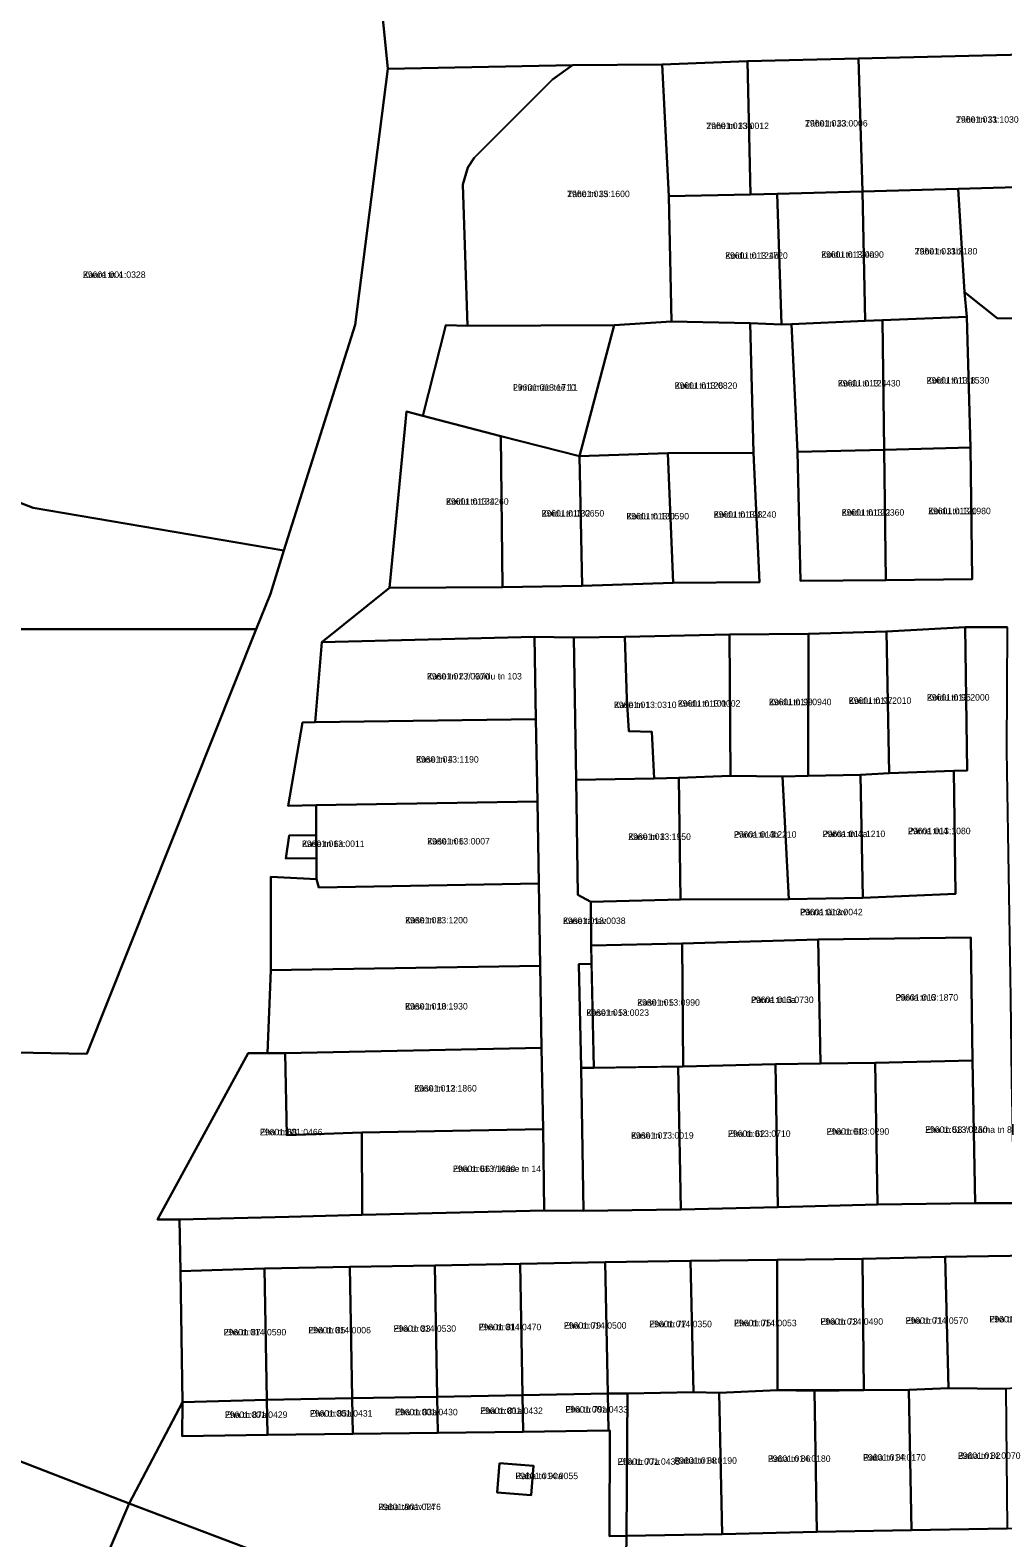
# Model space of a CAD drawing. Extents: x 518839 to 525192, y 6573164 to 6576561.
# Drawn here: x 523288.9 to 523514.2, y 6573652.7 to 6574001.8 of the extents above; entities that cross this region are included whole.
import ezdxf

# ---------------------------------------------------------------- set-up
doc = ezdxf.new("R2010")
doc.units = 0
for name, color, linetype in [('L_AADRESS', 7, 'Continuous'), ('PIIR', 7, 'Continuous'), ('TUNNUS', 7, 'Continuous')]:
    doc.layers.add(name, color=color, linetype=linetype)

msp = doc.modelspace()

# ---------------------------------------------------------------- linework, layer by layer
at = {"layer": 'PIIR'}
for points in [[(523179.73, 6573986.9), (523184.22, 6574005.85), (523276.05, 6574005.07), (523309.21, 6574005.43), (523309.74, 6574006.34), (523370.33, 6574007.54), (523371.79, 6573992.85), (523364.2, 6573933.56), (523347.71, 6573881.28), (523289.61, 6573891.15), (523234.3, 6573912.48), (523239.29, 6573978.07), (523222.16, 6573985.77)], [(523389.14, 6573966.07), (523390.31, 6573969.97), (523391.75, 6573972.24), (523409.91, 6573990.37), (523414.5, 6573993.67), (523435.27, 6573993.85), (523436.86, 6573963.35), (523437.44, 6573934.33), (523424.21, 6573933.47), (523390.19, 6573933.31)], [(523435.27, 6573993.85), (523455.07, 6573994.57), (523455.77, 6573963.73), (523436.86, 6573963.35)], [(523455.07, 6573994.57), (523480.74, 6573995.19), (523481.7, 6573964.38), (523461.92, 6573963.85), (523455.77, 6573963.73)], [(523480.74, 6573995.19), (523525.52, 6573996.29), (523525.53, 6573965.66), (523503.85, 6573965.03), (523481.7, 6573964.38)], [(523505.33, 6573941.1), (523503.85, 6573965.03), (523525.53, 6573965.66), (523525.92, 6573941.42), (523520.6, 6573934.94), (523512.9, 6573935.07)], [(523437.44, 6573934.33), (523436.86, 6573963.35), (523455.77, 6573963.73), (523461.92, 6573963.85), (523462.92, 6573933.6), (523455.7, 6573933.92)], [(523462.92, 6573933.6), (523461.92, 6573963.85), (523481.7, 6573964.38), (523482.35, 6573934.46), (523465.27, 6573933.72)], [(523482.35, 6573934.46), (523481.7, 6573964.38), (523503.85, 6573965.03), (523505.33, 6573941.1), (523505.87, 6573935.43), (523486.35, 6573934.6)], [(523164.89, 6573924.93), (523168.13, 6573938.02), (523234.3, 6573912.48), (523289.61, 6573891.15), (523347.71, 6573881.28), (523344.56, 6573871.27), (523341.27, 6573863.07), (523227.95, 6573863.09), (523197.91, 6573875.12), (523213.55, 6573906.24)], [(523416.19, 6573903.12), (523424.21, 6573933.47), (523437.44, 6573934.33), (523455.7, 6573933.92), (523456.42, 6573903.94), (523436.62, 6573903.87)], [(523465.27, 6573933.72), (523482.35, 6573934.46), (523486.35, 6573934.6), (523486.71, 6573904.58), (523466.63, 6573904.16)], [(523486.35, 6573934.6), (523505.87, 6573935.43), (523506.74, 6573905.15), (523486.71, 6573904.58)], [(523379.86, 6573912.46), (523385.21, 6573933.5), (523390.19, 6573933.31), (523424.21, 6573933.47), (523416.19, 6573903.12), (523397.97, 6573907.79)], [(523376.1, 6573913.49), (523379.86, 6573912.46), (523397.97, 6573907.79), (523398.35, 6573872.77), (523372.13, 6573872.63)], [(523416.19, 6573903.12), (523416.78, 6573873.13), (523398.35, 6573872.77), (523397.97, 6573907.79)], [(523416.78, 6573873.13), (523416.19, 6573903.12), (523436.62, 6573903.87), (523437.86, 6573873.83)], [(523436.62, 6573903.87), (523456.42, 6573903.94), (523457.86, 6573873.97), (523437.86, 6573873.83)], [(523466.63, 6573904.16), (523486.71, 6573904.58), (523487.11, 6573874.4), (523467.33, 6573874.29)], [(523486.71, 6573904.58), (523506.74, 6573905.15), (523507.11, 6573874.68), (523487.11, 6573874.4)], [(523356.5, 6573860.09), (523405.73, 6573861.31), (523406.06, 6573842.21), (523354.92, 6573841.56)], [(523405.73, 6573861.31), (523414.83, 6573861.12), (523415.36, 6573828.22), (523415.74, 6573801.54), (523418.77, 6573799.99), (523418.85, 6573789.88), (523418.94, 6573785.63), (523416, 6573785.54), (523416.55, 6573761.52), (523417.09, 6573728.42), (523408.01, 6573728.5), (523407.72, 6573747.32), (523407.37, 6573766.12), (523407.07, 6573785.14), (523406.73, 6573804.17), (523406.39, 6573823.19), (523406.06, 6573842.21)], [(523414.83, 6573861.12), (523426.68, 6573861.32), (523427.15, 6573846.93), (523427.58, 6573839.5), (523432.87, 6573839.31), (523433.44, 6573828.47), (523415.36, 6573828.22)], [(523418.77, 6573799.99), (523439.53, 6573800.47), (523464.67, 6573800.57), (523481.77, 6573800.88), (523503.2, 6573801.82), (523502.82, 6573830.27), (523505.95, 6573830.39), (523505.5, 6573863.51), (523515.24, 6573863.54), (523515.05, 6573835.01), (523515.36, 6573815.85), (523515.68, 6573796.84), (523516, 6573777.76), (523516.2, 6573758.68), (523516.72, 6573730.15), (523507.79, 6573730.18), (523507.17, 6573763.2), (523506.82, 6573791.66), (523471.42, 6573791.21), (523439.93, 6573790.32), (523418.85, 6573789.88)], [(523432.87, 6573839.31), (523427.58, 6573839.5), (523427.15, 6573846.93), (523426.68, 6573861.32), (523450.86, 6573861.88), (523451.16, 6573829.1), (523439.14, 6573828.67), (523433.44, 6573828.47)], [(523469.17, 6573861.99), (523469.15, 6573829.11), (523463.15, 6573829), (523451.16, 6573829.1), (523450.86, 6573861.88)], [(523469.17, 6573861.99), (523487.28, 6573862.58), (523487.87, 6573829.74), (523481.25, 6573829.33), (523469.15, 6573829.11)], [(523487.28, 6573862.58), (523505.5, 6573863.51), (523505.95, 6573830.39), (523502.82, 6573830.27), (523487.87, 6573829.74)], [(523406.39, 6573823.19), (523355.15, 6573822.36), (523348.65, 6573822.17), (523351.99, 6573841.51), (523354.92, 6573841.56), (523406.06, 6573842.21)], [(523481.25, 6573829.33), (523487.87, 6573829.74), (523502.82, 6573830.27), (523503.2, 6573801.82), (523481.77, 6573800.88)], [(523415.74, 6573801.54), (523415.36, 6573828.22), (523433.44, 6573828.47), (523439.14, 6573828.67), (523439.53, 6573800.47), (523418.77, 6573799.99)], [(523464.67, 6573800.57), (523439.53, 6573800.47), (523439.14, 6573828.67), (523451.16, 6573829.1), (523463.15, 6573829)], [(523464.67, 6573800.57), (523463.15, 6573829), (523469.15, 6573829.11), (523481.25, 6573829.33), (523481.77, 6573800.88)], [(523406.73, 6573804.17), (523355.78, 6573803.27), (523355.27, 6573805.23), (523355.23, 6573810.03), (523355.2, 6573815.35), (523355.15, 6573822.36), (523406.39, 6573823.19)], [(523355.23, 6573810.03), (523348.14, 6573809.95), (523348.94, 6573815.29), (523355.2, 6573815.35)], [(523407.07, 6573785.14), (523344.66, 6573784.16), (523344.66, 6573805.77), (523355.27, 6573805.23), (523355.78, 6573803.27), (523406.73, 6573804.17)], [(523439.93, 6573790.32), (523471.42, 6573791.21), (523471.96, 6573762.5), (523461.57, 6573762.38), (523440.2, 6573761.84)], [(523471.96, 6573762.5), (523471.42, 6573791.21), (523506.82, 6573791.66), (523507.17, 6573763.2), (523484.64, 6573762.64)], [(523418.85, 6573789.88), (523439.93, 6573790.32), (523440.2, 6573761.84), (523419.49, 6573761.55)], [(523407.37, 6573766.12), (523348.02, 6573764.94), (523343.91, 6573764.89), (523344.66, 6573784.16), (523407.07, 6573785.14)], [(523416, 6573785.54), (523418.94, 6573785.63), (523419.49, 6573761.55), (523416.55, 6573761.52)], [(523318.43, 6573726.44), (523339.41, 6573764.94), (523343.91, 6573764.89), (523348.02, 6573764.94), (523348.34, 6573745.93), (523365.76, 6573746.55), (523365.86, 6573727.92), (523365.86, 6573727.48), (523348.82, 6573727.06), (523323.51, 6573726.43)], [(523407.72, 6573747.32), (523365.76, 6573746.55), (523348.34, 6573745.93), (523348.02, 6573764.94), (523407.37, 6573766.12)], [(523484.64, 6573762.64), (523507.17, 6573763.2), (523507.79, 6573730.18), (523485.19, 6573729.87)], [(523416.55, 6573761.52), (523419.49, 6573761.55), (523438.97, 6573761.82), (523439.66, 6573728.72), (523417.09, 6573728.42)], [(523440.2, 6573761.84), (523461.57, 6573762.38), (523462.11, 6573729.23), (523439.66, 6573728.72), (523438.97, 6573761.82)], [(523461.57, 6573762.38), (523471.96, 6573762.5), (523484.64, 6573762.64), (523485.19, 6573729.87), (523462.11, 6573729.23)], [(523365.86, 6573727.92), (523365.76, 6573746.55), (523407.72, 6573747.32), (523408.01, 6573728.5), (523365.86, 6573727.48)], [(523500.82, 6573717.74), (523501.64, 6573687.34), (523492.44, 6573686.99), (523481.99, 6573686.88), (523481.67, 6573717.28)], [(523500.82, 6573717.74), (523520.95, 6573718.1), (523521.36, 6573687.69), (523514.89, 6573687.17), (523501.64, 6573687.34)], [(523343.2, 6573715.06), (523343.76, 6573684.65), (523324.24, 6573684.13), (523323.72, 6573714.44)], [(523362.93, 6573715.42), (523363.49, 6573685.01), (523343.76, 6573684.65), (523343.2, 6573715.06)], [(523382.66, 6573715.78), (523383.22, 6573685.37), (523363.49, 6573685.01), (523362.93, 6573715.42)], [(523402.39, 6573716.14), (523402.95, 6573685.73), (523383.22, 6573685.37), (523382.66, 6573715.78)], [(523422.12, 6573716.5), (523422.68, 6573686.09), (523402.95, 6573685.73), (523402.39, 6573716.14)], [(523441.85, 6573716.86), (523442.52, 6573686.44), (523427.29, 6573686.12), (523422.68, 6573686.09), (523422.12, 6573716.5)], [(523441.85, 6573716.86), (523461.94, 6573717.06), (523462.02, 6573686.91), (523448.49, 6573686.25), (523442.52, 6573686.44)], [(523481.67, 6573717.28), (523481.99, 6573686.88), (523462.02, 6573686.91), (523461.94, 6573717.06)], [(523427.01, 6573653.13), (523427.29, 6573686.12), (523442.52, 6573686.44), (523448.49, 6573686.25), (523449.21, 6573653.56)], [(523448.49, 6573686.25), (523462.02, 6573686.91), (523470.6, 6573686.76), (523471.1, 6573654.07), (523449.21, 6573653.56)], [(523470.6, 6573686.76), (523481.99, 6573686.88), (523492.44, 6573686.99), (523493.08, 6573654.49), (523471.1, 6573654.07)], [(523492.44, 6573686.99), (523501.64, 6573687.34), (523514.89, 6573687.17), (523515.17, 6573654.87), (523493.08, 6573654.49)], [(523311.86, 6573660.69), (523324.24, 6573684.13), (523324.17, 6573676.26), (523343.91, 6573676.52), (523363.66, 6573676.77), (523383.38, 6573677.03), (523403.11, 6573677.28), (523422.84, 6573677.54), (523423.19, 6573677.54), (523423.12, 6573653.08), (523427.01, 6573653.13), (523426.74, 6573634.12), (523341.16, 6573649.51)], [(523343.91, 6573676.52), (523324.17, 6573676.26), (523324.24, 6573684.13), (523343.76, 6573684.65)], [(523363.49, 6573685.01), (523363.66, 6573676.77), (523343.91, 6573676.52), (523343.76, 6573684.65)], [(523363.49, 6573685.01), (523383.22, 6573685.37), (523383.38, 6573677.03), (523363.66, 6573676.77)], [(523383.22, 6573685.37), (523402.95, 6573685.73), (523403.11, 6573677.28), (523383.38, 6573677.03)], [(523402.95, 6573685.73), (523422.68, 6573686.09), (523422.84, 6573677.54), (523403.11, 6573677.28)], [(523422.68, 6573686.09), (523427.29, 6573686.12), (523427.01, 6573653.13), (523423.12, 6573653.08), (523423.19, 6573677.54), (523422.84, 6573677.54)], [(523311.86, 6573660.69), (523305.53, 6573645.86), (523336.43, 6573633.91), (523333.39, 6573624.09), (523269.08, 6573649.78), (523281.29, 6573672.44)], [(523397.66, 6573669.98), (523405.53, 6573669.34), (523404.98, 6573662.59), (523397.11, 6573663.22)], [(523397.66, 6573669.98), (523397.11, 6573663.22), (523404.98, 6573662.59), (523405.53, 6573669.34)], [(523341.16, 6573649.51), (523336.43, 6573633.91), (523305.53, 6573645.86), (523311.86, 6573660.69)], [(523426.74, 6573634.12), (523427.01, 6573653.13), (523449.21, 6573653.56), (523471.1, 6573654.07), (523493.08, 6573654.49), (523515.17, 6573654.87), (523537.06, 6573655.2), (523559.13, 6573655.37), (523581.36, 6573655.75), (523581.46, 6573636.75)]]:
    msp.add_lwpolyline(points, close=True, dxfattribs=at)
for points in [[(523676.04, 6573998.47), (523670.16, 6573998.46), (523628.17, 6573997.67), (523585.64, 6573997.1), (523575.15, 6573996.53), (523546.14, 6573996.29), (523525.52, 6573996.29), (523480.74, 6573995.19), (523455.07, 6573994.57), (523435.27, 6573993.85), (523414.5, 6573993.67), (523371.79, 6573992.85), (523370.33, 6574007.54)], [(523231.38, 6573766.09), (523302.09, 6573764.74), (523341.27, 6573863.07), (523344.56, 6573871.27), (523347.71, 6573881.28), (523364.2, 6573933.56), (523371.79, 6573992.85), (523414.5, 6573993.67), (523409.91, 6573990.37), (523391.75, 6573972.24), (523390.31, 6573969.97), (523389.14, 6573966.07), (523390.19, 6573933.31), (523385.21, 6573933.5), (523379.86, 6573912.46), (523376.1, 6573913.49), (523372.13, 6573872.63), (523356.5, 6573860.09), (523354.92, 6573841.56), (523351.99, 6573841.51), (523348.65, 6573822.17), (523355.15, 6573822.36), (523355.2, 6573815.35), (523348.94, 6573815.29), (523348.14, 6573809.95), (523355.23, 6573810.03), (523355.27, 6573805.23), (523344.66, 6573805.77), (523344.66, 6573784.16), (523343.91, 6573764.89), (523339.41, 6573764.94), (523318.43, 6573726.44), (523323.51, 6573726.43), (523323.72, 6573714.44), (523324.24, 6573684.13), (523311.86, 6573660.69), (523281.29, 6573672.44)], [(523515.24, 6573863.54), (523505.5, 6573863.51), (523487.28, 6573862.58), (523469.17, 6573861.99), (523450.86, 6573861.88), (523426.68, 6573861.32), (523414.83, 6573861.12), (523405.73, 6573861.31), (523356.5, 6573860.09), (523372.13, 6573872.63), (523398.35, 6573872.77), (523416.78, 6573873.13), (523437.86, 6573873.83), (523457.86, 6573873.97), (523456.42, 6573903.94), (523455.7, 6573933.92), (523462.92, 6573933.6), (523465.27, 6573933.72), (523466.63, 6573904.16), (523467.33, 6573874.29), (523487.11, 6573874.4), (523507.11, 6573874.68), (523506.74, 6573905.15), (523505.87, 6573935.43), (523505.33, 6573941.1), (523512.9, 6573935.07), (523520.6, 6573934.94)], [(523227.95, 6573863.09), (523341.27, 6573863.07), (523302.09, 6573764.74), (523231.38, 6573766.09)], [(523520.95, 6573718.1), (523500.82, 6573717.74), (523481.67, 6573717.28), (523461.94, 6573717.06), (523441.85, 6573716.86), (523422.12, 6573716.5), (523402.39, 6573716.14), (523382.66, 6573715.78), (523362.93, 6573715.42), (523343.2, 6573715.06), (523323.72, 6573714.44), (523323.51, 6573726.43), (523348.82, 6573727.06), (523365.86, 6573727.48), (523408.01, 6573728.5), (523417.09, 6573728.42), (523439.66, 6573728.72), (523462.11, 6573729.23), (523485.19, 6573729.87), (523507.79, 6573730.18), (523516.72, 6573730.15)]]:
    msp.add_lwpolyline(points, dxfattribs=at)

# ---------------------------------------------------------------- texts
at = {"layer": 'L_AADRESS'}
for s, p in [('Tähe tn 33a', (523445.52, 6573978.87)), ('Tähe tn 33', (523468.39, 6573979.46)), ('Tähe tn 31', (523503.36, 6573980.33)), ('Tähe tn 35', (523413.29, 6573963.11)), ('Koidu tn 124b', (523449.89, 6573948.83)), ('Koidu tn 124a', (523472.14, 6573949.07)), ('Tähe tn 31b', (523493.79, 6573949.83)), ('Kaare tn 4', (523301.16, 6573944.41)), ('Koidu tn 126', (523438.19, 6573918.73)), ('Koidu tn 124', (523475.99, 6573919.27)), ('Koidu tn 118', (523496.55, 6573919.95)), ('Linnamäe tee 11', (523400.78, 6573918.31)), ('Koidu tn 134', (523385.24, 6573891.89)), ('Koidu tn 132', (523407.38, 6573889.16)), ('Koidu tn 130', (523427.02, 6573888.49)), ('Koidu tn 128', (523447.24, 6573888.9)), ('Koidu tn 122', (523476.87, 6573889.36)), ('Koidu tn 120', (523496.91, 6573889.7)), ('Kase tn 2 // Koidu tn 103', (523380.83, 6573851.43)), ('Koidu tn 99', (523460.02, 6573845.48)), ('Koidu tn 97', (523478.51, 6573845.79)), ('Koidu tn 95', (523496.62, 6573846.55)), ('Kase tn 1', (523424.13, 6573844.81)), ('Koidu tn 101', (523438.92, 6573845.13)), ('Kase tn 4', (523378.31, 6573832.19)), ('Kase tn 3', (523427.45, 6573814.29)), ('Pärna tn 4b', (523451.91, 6573814.81)), ('Pärna tn 4a', (523472.46, 6573814.94)), ('Pärna tn 4', (523492.23, 6573815.62)), ('Kase tn 6a', (523351.88, 6573812.65)), ('Kase tn 6', (523380.89, 6573813.23)), ('Pärna tänav', (523467.24, 6573796.84)), ('Kase tn 8', (523375.78, 6573794.96)), ('Kase tänav', (523412.33, 6573794.82)), ('Kase tn 5', (523429.53, 6573775.9)), ('Pärna tn 6a', (523455.88, 6573776.53)), ('Pärna tn 6', (523489.34, 6573777.08)), ('Kase tn 10', (523375.77, 6573775.02)), ('Kase tn 5a', (523417.75, 6573773.56)), ('Kase tn 12', (523377.86, 6573756.03)), ('Eha tn 68', (523342.14, 6573745.9)), ('Kase tn 7', (523428.1, 6573745.12)), ('Eha tn 62', (523450.54, 6573745.53)), ('Eha tn 60', (523473.38, 6573746.03)), ('Eha tn 58 // Pärna tn 8', (523496.21, 6573746.47)), ('Eha tn 66 // Kase tn 14', (523386.84, 6573737.4)), ('Eha tn 71', (523491.66, 6573702.25)), ('Eha tn 69', (523511.09, 6573702.57)), ('Eha tn 87', (523333.74, 6573699.57)), ('Eha tn 85', (523353.35, 6573700.04)), ('Eha tn 83', (523373.07, 6573700.4)), ('Eha tn 81', (523392.8, 6573700.76)), ('Eha tn 79', (523412.54, 6573701.12)), ('Eha tn 77', (523432.32, 6573701.46)), ('Eha tn 75', (523451.94, 6573701.69)), ('Eha tn 73', (523471.96, 6573702.03)), ('Eha tn 81a', (523393.16, 6573681.38)), ('Eha tn 79a', (523412.89, 6573681.69)), ('Eha tn 87a', (523334.02, 6573680.46)), ('Eha tn 85a', (523353.7, 6573680.77)), ('Eha tn 83a', (523373.44, 6573681.07)), ('Raba tn 82', (523503.8, 6573670.99)), ('Eha tn 77a', (523424.98, 6573669.6)), ('Raba tn 88', (523438.11, 6573669.85)), ('Raba tn 86', (523459.8, 6573670.3)), ('Raba tn 84', (523481.84, 6573670.58)), ('Raba tn 90a', (523401.32, 6573666.29)), ('Raba tänav T4', (523369.55, 6573659.12))]:
    msp.add_text(s, height=1.5, dxfattribs=at).set_placement(p)
at = {"layer": 'TUNNUS'}
for s, p in [('29601:013:0012', (523445.52, 6573978.87)), ('29601:013:0006', (523468.39, 6573979.46)), ('29601:013:1030', (523503.36, 6573980.33)), ('29601:013:1600', (523413.29, 6573963.11)), ('29601:013:1720', (523449.89, 6573948.83)), ('29601:013:0090', (523472.14, 6573949.07)), ('29601:013:2180', (523493.79, 6573949.83)), ('29601:001:0328', (523301.16, 6573944.41)), ('29601:013:0820', (523438.19, 6573918.73)), ('29601:013:1430', (523475.99, 6573919.27)), ('29601:013:1530', (523496.55, 6573919.95)), ('29601:013:1710', (523400.78, 6573918.31)), ('29601:013:1260', (523385.24, 6573891.89)), ('29601:013:0650', (523407.38, 6573889.16)), ('29601:013:0590', (523427.02, 6573888.49)), ('29601:013:1240', (523447.24, 6573888.9)), ('29601:013:0360', (523476.87, 6573889.36)), ('29601:013:1980', (523496.91, 6573889.7)), ('29601:013:0370', (523380.83, 6573851.43)), ('29601:013:0940', (523460.02, 6573845.48)), ('29601:013:2010', (523478.51, 6573845.79)), ('29601:013:2000', (523496.62, 6573846.55)), ('29601:013:0310', (523424.13, 6573844.81)), ('29601:013:0002', (523438.92, 6573845.13)), ('29601:013:1190', (523378.31, 6573832.19)), ('29601:013:1950', (523427.45, 6573814.29)), ('29601:013:2210', (523451.91, 6573814.81)), ('29601:013:1210', (523472.46, 6573814.94)), ('29601:013:1080', (523492.23, 6573815.62)), ('29601:013:0011', (523351.88, 6573812.65)), ('29601:013:0007', (523380.89, 6573813.23)), ('29601:013:0042', (523467.24, 6573796.84)), ('29601:013:1200', (523375.78, 6573794.96)), ('29601:013:0038', (523412.33, 6573794.82)), ('29601:013:0990', (523429.53, 6573775.9)), ('29601:013:0730', (523455.88, 6573776.53)), ('29601:013:1870', (523489.34, 6573777.08)), ('29601:013:1930', (523375.77, 6573775.02)), ('29601:013:0023', (523417.75, 6573773.56)), ('29601:013:1860', (523377.86, 6573756.03)), ('29601:001:0466', (523342.14, 6573745.9)), ('29601:013:0019', (523428.1, 6573745.12)), ('29601:013:0710', (523450.54, 6573745.53)), ('29601:013:0290', (523473.38, 6573746.03)), ('29601:013:0160', (523496.21, 6573746.47)), ('29601:013:1890', (523386.84, 6573737.4)), ('29601:014:0570', (523491.66, 6573702.25)), ('29601:014:0630', (523511.09, 6573702.57)), ('29601:014:0590', (523333.74, 6573699.57)), ('29601:014:0006', (523353.35, 6573700.04)), ('29601:014:0530', (523373.07, 6573700.4)), ('29601:014:0470', (523392.8, 6573700.76)), ('29601:014:0500', (523412.54, 6573701.12)), ('29601:014:0350', (523432.32, 6573701.46)), ('29601:014:0053', (523451.94, 6573701.69)), ('29601:014:0490', (523471.96, 6573702.03)), ('29601:001:0432', (523393.16, 6573681.38)), ('29601:001:0433', (523412.89, 6573681.69)), ('29601:001:0429', (523334.02, 6573680.46)), ('29601:001:0431', (523353.7, 6573680.77)), ('29601:001:0430', (523373.44, 6573681.07)), ('29601:014:0070', (523503.8, 6573670.99)), ('29601:001:0435', (523424.98, 6573669.6)), ('29601:014:0190', (523438.11, 6573669.85)), ('29601:014:0180', (523459.8, 6573670.3)), ('29601:014:0170', (523481.84, 6573670.58)), ('29601:014:0055', (523401.32, 6573666.29)), ('29601:001:0276', (523369.55, 6573659.12))]:
    msp.add_text(s, height=1.5, dxfattribs=at).set_placement(p)

doc.saveas('drawing.dxf')
